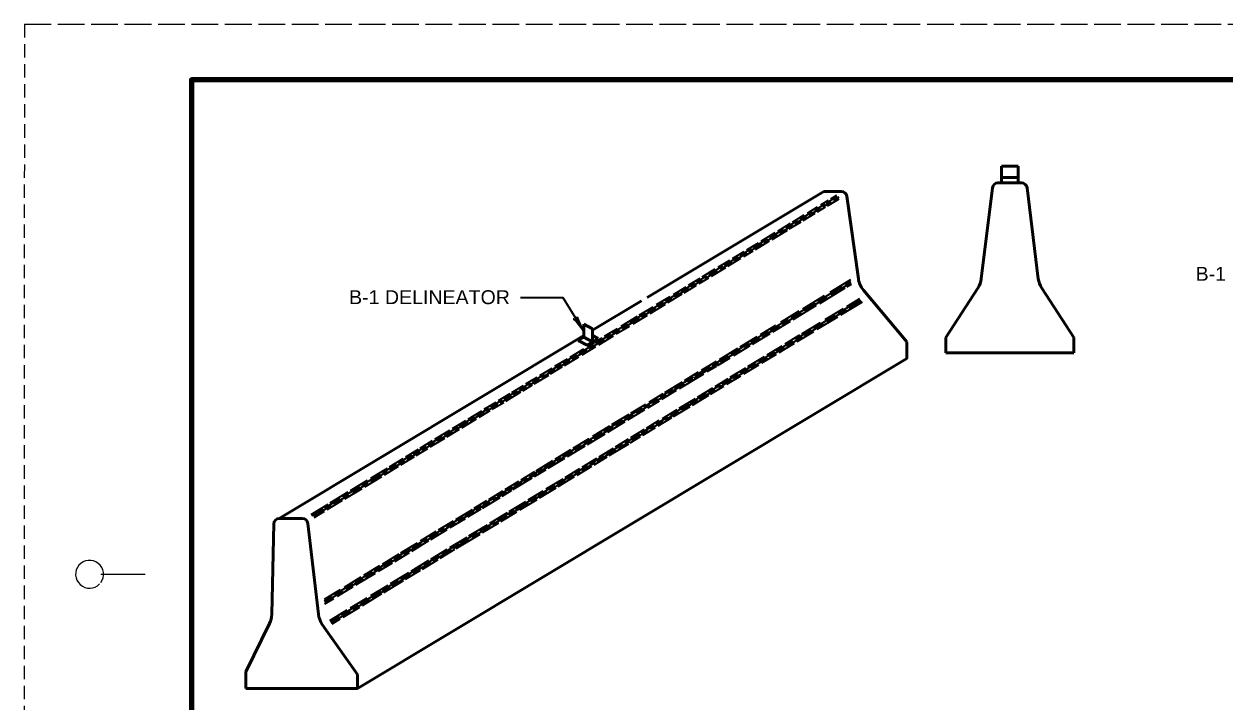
# Model space of a CAD drawing. Extents: x -60 to 620, y -42 to 398.
# Drawn here: x -60.3 to 155.3, y 276.6 to 398.3 of the extents above; entities that cross this region are included whole.
import ezdxf
from ezdxf.enums import TextEntityAlignment as Align

# ---------------------------------------------------------------- set-up
doc = ezdxf.new("R2010")
doc.units = 0
doc.header["$LTSCALE"] = 0.8
doc.linetypes.add('LONG_DASHED', pattern=[7.5, 6, -1.5])
doc.linetypes.add('MEDIUM_DASHED', pattern=[4.5, 3, -1.5])
doc.layers.add('1', color=7, linetype='Continuous', lineweight=35)
doc.layers.add('61', color=7, linetype='Continuous', lineweight=35)

msp = doc.modelspace()

# ---------------------------------------------------------------- linework, layer by layer
at = {"layer": '1', "linetype": 'MEDIUM_DASHED', "lineweight": 13}
msp.add_line((-60.2155, 398.2688), (-60.2755, -41.7713), dxfattribs=at)
at = {"layer": '1', "lineweight": 53}
for p, q in [((115.1369, 372.7462), (115.1369, 369.7462)), ((115.1369, 372.7462), (118.1369, 372.7462)), ((115.1369, 370.7462), (118.1369, 370.7462)), ((118.1369, 372.7462), (118.1369, 369.7462)), ((111.5132, 352.5558), (113.5285, 368.8687)), ((114.521, 369.7462), (118.7528, 369.7462)), ((121.7606, 352.5558), (119.7453, 368.8687)), ((51.5427, 349.1747), (83.2579, 368.231)), ((83.258, 368.2311), (86.3888, 368.2311)), ((87.379, 367.3702), (89.4643, 352.5318)), ((90.3607, 350.5181), (98.1369, 341.2462)), ((105.1369, 341.9962), (110.8982, 350.8678)), ((128.1369, 341.9962), (122.3757, 350.8678)), ((41.7647, 343.2994), (50.5427, 348.5738)), ((40.2022, 342.0675), (40.2022, 344.4112)), ((40.2022, 344.4112), (41.7647, 343.5703)), ((41.7647, 341.2266), (41.7647, 343.5703)), ((-14.4591, 309.5168), (40.2022, 342.3607)), ((39.1975, 341.4638), (40.2022, 342.0675)), ((39.1975, 341.4638), (40.7686, 340.6088)), ((40.2022, 342.0675), (41.7647, 341.2266)), ((40.7629, 340.6182), (41.7647, 341.2266)), ((41.7592, 341.2359), (42.7609, 341.8442)), ((41.7647, 342.3864), (42.7609, 341.8442)), ((105.1369, 339.2462), (105.1369, 341.9962)), ((128.1369, 339.2462), (128.1369, 341.9962)), ((105.1369, 339.2462), (128.1369, 339.2462)), ((-15.8152, 292.3312), (-15.4588, 308.5387)), ((-14.4591, 309.5168), (-10.3276, 309.5168)), ((-7.4372, 292.3503), (-9.3343, 308.6325)), ((-20.4373, 282.0168), (-16.219, 290.6656)), ((-0.4373, 281.5168), (-6.7407, 290.5188)), ((-20.4373, 279.0168), (-20.4373, 282.0168)), ((-0.4373, 279.0168), (-0.4373, 281.5168)), ((-20.4373, 279.0168), (-0.4373, 279.0168))]:
    msp.add_line(p, q, dxfattribs=at)
at = {"layer": '1'}
for p, q in [((82.7095, 365.7921), (84.1125, 366.644)), ((83.7058, 366.1046), (85.6554, 367.2884)), ((83.9053, 365.6407), (85.9958, 366.9101)), ((84.5417, 366.9047), (85.572, 367.5302)), ((85.0686, 366.6396), (86.0474, 367.2339)), ((79.0243, 363.2619), (81.1655, 364.5621)), ((79.5882, 363.0192), (81.7362, 364.3236)), ((80.317, 364.3393), (82.1538, 365.4547)), ((80.6573, 363.961), (82.727, 365.2177)), ((81.6363, 364.8479), (83.482, 365.9687)), ((82.1379, 364.5675), (83.5915, 365.4502)), ((83.1213, 365.4572), (84.6097, 366.361)), ((75.0146, 361.1196), (77.3105, 362.5138)), ((75.3733, 360.7525), (77.6758, 362.1506)), ((76.5091, 361.7346), (78.6042, 363.0068)), ((77.0618, 361.4853), (79.1799, 362.7714)), ((77.6497, 362.7197), (79.7679, 364.0059)), ((78.149, 362.4379), (80.2372, 363.7058)), ((72.0462, 359.3171), (74.5393, 360.831)), ((72.564, 359.0467), (74.9811, 360.5143)), ((73.5511, 359.9384), (76.0314, 361.4445)), ((73.9928, 359.6217), (76.72, 361.2777)), ((68.2706, 356.7321), (70.2956, 357.9617)), ((69.4199, 357.7223), (71.5307, 359.0041)), ((69.871, 357.4115), (72.189, 358.819)), ((70.6348, 358.1677), (73.1818, 359.7142)), ((71.0264, 357.8205), (73.5382, 359.3457)), ((64.3326, 354.6332), (66.3972, 355.8869)), ((65.4373, 355.0117), (67.8893, 356.5006)), ((66.0403, 354.7928), (68.3869, 356.2177)), ((66.9039, 356.1946), (68.9752, 357.4522)), ((67.2186, 355.8009), (69.5362, 357.2082)), ((68.8917, 356.5242), (70.566, 357.5409)), ((61.453, 352.8847), (63.7905, 354.3041)), ((61.9748, 352.6167), (64.1997, 353.9677)), ((62.6412, 353.3137), (65.1529, 354.8389)), ((63.1273, 353.024), (65.6833, 354.5761)), ((64.7087, 354.2769), (66.813, 355.5546)), ((57.667, 350.2933), (60.1002, 351.7708)), ((58.1795, 350.0196), (60.4123, 351.3754)), ((58.9768, 351.3812), (61.05, 352.64)), ((59.4439, 351.08), (61.5217, 352.3417)), ((60.451, 351.9838), (62.2686, 353.0875)), ((60.9062, 351.6753), (62.6182, 352.7149)), ((84.3843, 350.1377), (88.0927, 352.3895)), ((84.5558, 349.6568), (88.1685, 351.8505)), ((87.1312, 351.513), (88.1307, 352.1199)), ((87.4198, 351.1035), (88.2098, 351.5832)), ((53.2662, 347.9136), (55.6943, 349.388)), ((54.8354, 348.574), (57.3162, 350.0804)), ((55.2881, 348.2638), (57.867, 349.8297)), ((56.2621, 349.7328), (58.5403, 351.1162)), ((56.5431, 349.3186), (59.0574, 350.8453)), ((79.4742, 347.1562), (83.3711, 349.5224)), ((79.8356, 346.7906), (83.8847, 349.2492)), ((82.221, 348.5315), (86.5327, 351.1496)), ((82.522, 348.1295), (87.0777, 350.8957)), ((50.15, 346.0214), (52.6122, 347.5165)), ((50.5763, 345.6954), (53.1458, 347.2557)), ((51.6934, 346.6662), (54.4914, 348.3652)), ((52.0862, 346.3196), (54.8656, 348.0072)), ((53.5778, 347.518), (56.0683, 349.0302)), ((77.4281, 345.6212), (81.7329, 348.2352)), ((77.7449, 345.2287), (81.9681, 347.7931)), ((83.4892, 345.2069), (86.7786, 347.2043)), ((85.8528, 346.3497), (89.8738, 348.7912)), ((86.3438, 346.0628), (90.1988, 348.4037)), ((87.3866, 347.5735), (89.7112, 348.9851)), ((87.8146, 347.2483), (90.0363, 348.5974)), ((46.9054, 344.0512), (49.7972, 345.8072)), ((47.1507, 343.6153), (50.1759, 345.4522)), ((48.4893, 344.7207), (51.2899, 346.4212)), ((49.0588, 344.4813), (51.5948, 346.0213)), ((73.6775, 343.3438), (76.8702, 345.2823)), ((74.0979, 343.0143), (77.2602, 344.9344)), ((75.5359, 344.7648), (78.8249, 346.7619)), ((75.8467, 344.3684), (79.2529, 346.4367)), ((81.4554, 343.6795), (85.305, 346.017)), ((82.0862, 343.4776), (85.7741, 345.7169)), ((83.8669, 344.8512), (87.3238, 346.9502)), ((43.9002, 342.2264), (46.2312, 343.6418)), ((44.3267, 341.9006), (46.6382, 343.3042)), ((45.3607, 342.8209), (48.0362, 344.4455)), ((46.0281, 342.641), (48.365, 344.06)), ((70.19, 341.2261), (73.3333, 343.1347)), ((70.4884, 340.8225), (73.6143, 342.7206)), ((71.8853, 342.5481), (74.6733, 344.241)), ((72.2699, 342.1966), (75.3515, 344.0677)), ((78.1838, 341.6928), (81.0057, 343.4064)), ((78.5059, 341.3036), (81.4528, 343.093)), ((79.3247, 342.6782), (82.6405, 344.6916)), ((79.7837, 342.3719), (83.2048, 344.4493)), ((39.3402, 339.1651), (41.9953, 340.7773)), ((40.8491, 340.3737), (43.4779, 341.97)), ((41.2204, 340.0144), (43.8973, 341.6398)), ((42.3722, 341.0062), (45.0273, 342.6184)), ((42.8603, 340.7174), (45.5155, 342.3297)), ((66.6608, 339.0831), (69.8221, 341.0027)), ((67.1107, 338.7715), (70.0523, 340.5577)), ((68.2643, 340.3493), (71.3041, 342.1952)), ((69.0316, 340.2303), (71.7599, 341.8869)), ((74.7675, 339.6184), (77.677, 341.3851)), ((75.2291, 339.3138), (78.0023, 340.9977)), ((76.326, 340.8574), (78.9598, 342.4567)), ((76.6161, 340.4485), (79.4189, 342.1504)), ((36.4969, 337.4387), (38.968, 338.9392)), ((36.7063, 336.9807), (39.3137, 338.5639)), ((37.745, 338.4889), (40.2245, 339.9945)), ((38.1238, 338.1341), (40.7962, 339.7568)), ((39.8763, 338.9055), (42.3406, 340.4018)), ((63.2017, 336.9827), (66.1239, 338.7571)), ((64.5349, 338.0848), (67.834, 340.0881)), ((64.7141, 337.6087), (68.2929, 339.7818)), ((69.636, 336.7952), (72.622, 338.6083)), ((71.6299, 337.7133), (74.4291, 339.4129)), ((72.1565, 337.4482), (74.7634, 339.0312)), ((73.1114, 338.9055), (75.7955, 340.5352)), ((73.5435, 338.5828), (76.198, 340.1947)), ((32.2762, 335.1683), (34.509, 336.5241)), ((32.6422, 334.8056), (35.0575, 336.2722)), ((33.7278, 335.7572), (36.1197, 337.2097)), ((34.2228, 335.4727), (36.3932, 336.7905)), ((35.0178, 336.833), (37.2362, 338.18)), ((35.4147, 336.4891), (37.7367, 337.899)), ((60.0748, 334.7917), (64.3996, 337.4178)), ((60.1217, 335.1125), (62.8872, 336.7917)), ((61.3113, 336.1274), (64.0087, 337.7653)), ((62.3523, 335.8822), (64.0044, 336.8853)), ((64.197, 337.0023), (66.4608, 338.3769)), ((66.4467, 334.8586), (69.2756, 336.5763)), ((67.0792, 334.6576), (69.7692, 336.291)), ((68.2933, 335.6872), (71.0424, 337.3565)), ((68.9204, 335.4832), (71.599, 337.1096)), ((70.2004, 336.5528), (73.146, 338.3414)), ((29.7993, 333.6642), (31.8408, 334.9039)), ((30.3017, 333.3843), (32.213, 334.5449)), ((31.0119, 334.1081), (33.1593, 335.412)), ((31.2573, 333.672), (33.8914, 335.2715)), ((56.4812, 332.902), (59.89, 334.9718)), ((57.3891, 332.8684), (61.7312, 335.505)), ((58.2777, 334.2854), (60.7948, 335.8137)), ((58.8663, 334.0578), (59.8162, 334.6347)), ((63.7788, 333.2386), (66.1227, 334.6618)), ((64.4156, 333.0403), (66.6723, 334.4106)), ((65.0037, 333.6898), (67.8521, 335.4193)), ((65.8721, 333.6322), (68.3505, 335.1371)), ((24.9042, 330.6919), (26.9522, 331.9355)), ((25.8838, 330.9942), (28.2502, 332.4311)), ((26.1965, 330.599), (28.8851, 332.2315)), ((27.3006, 332.147), (29.3876, 333.4142)), ((27.5853, 331.7349), (29.8843, 333.1309)), ((28.652, 332.6751), (30.6281, 333.875)), ((29.2453, 332.4502), (30.9664, 333.4953)), ((51.9203, 330.4251), (54.4504, 331.9614)), ((53.9208, 331.3473), (56.1863, 332.7229)), ((54.2152, 330.9412), (56.8212, 332.5237)), ((54.742, 332.1384), (57.9, 334.056)), ((55.3786, 331.94), (58.2669, 333.6938)), ((59.307, 330.2306), (62.2014, 331.9881)), ((60.616, 331.3181), (63.3742, 332.9928)), ((60.9365, 330.9277), (63.7533, 332.6381)), ((62.567, 332.2101), (64.7479, 333.5343)), ((62.9487, 331.8571), (65.2973, 333.2833)), ((22.3254, 329.126), (24.4711, 330.4289)), ((22.7447, 328.7957), (24.8271, 330.0601)), ((23.4759, 329.5321), (25.5535, 330.7937)), ((23.7607, 329.12), (25.8126, 330.3659)), ((25.201, 330.2872), (27.2666, 331.5414)), ((48.6373, 328.4316), (51.3347, 330.0694)), ((49.66, 328.4676), (52.0928, 329.9448)), ((50.9945, 329.5704), (53.4824, 331.0811)), ((51.6678, 329.3944), (53.7568, 330.6629)), ((52.5064, 330.196), (55.0018, 331.7113)), ((55.7422, 328.0659), (59.1118, 330.1121)), ((57.3169, 329.3148), (60.2187, 331.0768)), ((57.8128, 329.0309), (60.6612, 330.7605)), ((59.6835, 329.8744), (62.6268, 331.6617)), ((17.8907, 326.1407), (20.5613, 327.7623)), ((19.4088, 327.355), (21.8923, 328.863)), ((19.8213, 327.0206), (22.3807, 328.5747)), ((20.9839, 328.0189), (23.1692, 329.3458)), ((21.4056, 327.6899), (23.3769, 328.887)), ((45.2451, 326.3717), (48.3058, 328.2303)), ((45.9309, 326.2032), (49.1115, 328.1346)), ((47.4922, 327.4437), (50.6879, 329.3842)), ((48.0932, 327.2238), (51.1593, 329.0856)), ((53.155, 326.495), (55.2911, 327.7921)), ((53.5395, 326.1437), (55.9719, 327.6207)), ((54.3102, 327.4891), (56.9292, 329.0793)), ((54.867, 327.2422), (57.2377, 328.6817)), ((56.2891, 327.8132), (59.2619, 329.6184)), ((15.1841, 324.4972), (17.617, 325.9745)), ((15.5884, 324.1577), (17.9079, 325.5661)), ((16.6094, 325.6552), (19.0258, 327.1225)), ((17.0728, 325.3517), (19.4429, 326.7908)), ((18.3118, 325.8113), (20.9615, 327.4203)), ((41.8039, 324.2822), (44.851, 326.1325)), ((42.0436, 323.8428), (45.4969, 325.9398)), ((43.7707, 325.184), (47.1257, 327.2212)), ((44.4841, 325.0322), (47.6344, 326.9452)), ((48.6283, 324.0388), (51.0849, 325.5306)), ((50.5531, 324.9151), (52.749, 326.2485)), ((50.8123, 324.4878), (53.0509, 325.8471)), ((51.4265, 325.738), (53.7422, 327.1442)), ((52.1772, 325.6088), (54.4503, 326.9892)), ((10.8331, 322.1477), (13.0508, 323.4943)), ((12.2523, 322.7169), (14.7464, 324.2314)), ((12.6286, 322.3604), (15.235, 323.9431)), ((13.4675, 323.7473), (16.1258, 325.3615)), ((13.9245, 323.44), (16.6247, 325.0796)), ((38.29, 322.1486), (41.1663, 323.8951)), ((38.6405, 321.7764), (41.6958, 323.6317)), ((40.1957, 323.0132), (43.5063, 325.0235)), ((40.8258, 322.8109), (43.9977, 324.737)), ((45.8757, 322.3675), (48.2274, 323.7955)), ((46.4507, 322.1316), (48.4797, 323.3637)), ((47.5926, 323.1174), (50.2389, 324.7242)), ((48.5202, 323.0959), (50.3562, 324.2107)), ((48.7997, 323.5579), (51.7037, 325.3213)), ((8.2545, 320.5819), (10.518, 321.9563)), ((8.5042, 320.1487), (10.8167, 321.5528)), ((9.6215, 321.1195), (11.8789, 322.4903)), ((10.1218, 320.8383), (12.2061, 322.1038)), ((11.2047, 321.7885), (13.4495, 323.1515)), ((35.0763, 320.1972), (37.8614, 321.8883)), ((35.4317, 319.828), (38.2497, 321.5391)), ((36.3515, 320.6789), (39.6864, 322.7039)), ((37.2616, 320.6467), (40.4403, 322.5768)), ((42.5857, 319.7847), (45.9462, 321.8252)), ((42.9639, 320.5994), (45.5001, 322.1394)), ((44.1792, 321.0447), (47.2117, 322.8862)), ((44.7616, 320.8137), (48.2428, 322.9275)), ((4.1507, 317.7976), (6.5964, 319.2827)), ((5.3382, 318.8112), (7.757, 320.2798)), ((5.4235, 318.278), (8.0932, 319.8991)), ((6.9564, 319.5012), (9.3386, 320.9477)), ((7.3249, 319.1399), (9.7994, 320.6425)), ((31.6217, 318.0995), (34.6095, 319.9137)), ((32.0692, 317.7862), (35.096, 319.6242)), ((33.0592, 318.6798), (36.0765, 320.5119)), ((33.8082, 318.5497), (36.8102, 320.3726)), ((38.5553, 317.6298), (40.8918, 319.0486)), ((39.8861, 318.7305), (42.5228, 320.3316)), ((39.8987, 318.1532), (42.316, 319.621)), ((41.2876, 319.2889), (43.7883, 320.8074)), ((42.0414, 319.1619), (44.3882, 320.5869)), ((0.3282, 315.4766), (3.648, 317.4923)), ((0.8827, 315.2282), (3.9381, 317.0835)), ((1.9412, 316.1635), (4.9437, 317.9867)), ((1.995, 316.7811), (4.9609, 318.5821)), ((4.4207, 317.3765), (6.9478, 318.911)), ((28.9562, 316.481), (31.3761, 317.9504)), ((29.4479, 316.1946), (31.7932, 317.6187)), ((30.4367, 317.0873), (32.7716, 318.5052)), ((31.3424, 317.0524), (33.4147, 318.3107)), ((35.4672, 315.7547), (38.2426, 317.4399)), ((35.5959, 315.2481), (38.5324, 317.0312)), ((36.8411, 316.8815), (39.4751, 318.4809)), ((37.2948, 316.572), (39.5609, 317.948)), ((38.9735, 317.299), (41.6609, 318.9308)), ((-3.0745, 313.4104), (-0.0261, 315.2614)), ((-2.7078, 313.048), (0.3935, 314.9312)), ((-1.6814, 314.5487), (1.3504, 316.3897)), ((-1.2796, 314.2077), (1.4686, 315.8765)), ((24.6424, 313.569), (27.3713, 315.226)), ((26.0701, 314.7285), (28.5092, 316.2096)), ((26.6252, 314.4806), (29.1331, 316.0034)), ((27.4795, 314.7067), (30.9313, 316.8028)), ((27.7244, 315.4404), (30.0201, 316.8344)), ((32.0238, 313.6638), (35.0086, 315.4762)), ((32.2227, 313.1998), (35.2428, 315.0337)), ((33.4593, 314.8281), (36.4578, 316.6488)), ((34.0617, 314.6088), (36.9117, 316.3393)), ((-6.2853, 311.4607), (-3.5342, 313.1313)), ((-5.8592, 311.1344), (-3.0917, 312.8149)), ((-5.309, 312.346), (-2.0953, 314.2974)), ((-4.6422, 312.1658), (-1.9706, 313.7882)), ((20.5269, 311.3626), (22.7783, 312.7297)), ((22.0384, 311.4028), (25.1617, 313.2993)), ((22.1424, 312.051), (24.416, 313.4316)), ((23.1482, 312.9543), (25.6507, 314.4738)), ((23.9101, 312.8319), (26.3851, 314.3347)), ((25.5261, 313.5206), (27.2835, 314.5877)), ((26.7879, 310.7772), (29.7869, 312.5983)), ((27.9374, 311.1825), (31.7394, 313.4912)), ((28.6962, 311.0585), (31.7979, 312.9418)), ((30.1872, 312.8413), (32.9048, 314.4914)), ((30.6677, 312.5479), (33.6202, 314.3407)), ((-8.7566, 310.2526), (-5.6928, 312.113)), ((-8.6058, 310.0517), (-6.6126, 311.262)), ((-8.283, 309.9552), (-5.1284, 311.8707)), ((-8.1818, 309.7241), (-6.3454, 310.8392)), ((17.2322, 309.362), (20.1982, 311.1631)), ((17.6347, 309.0214), (20.5132, 310.7693)), ((18.8483, 310.0507), (21.7809, 311.8314)), ((19.3896, 309.7944), (21.7624, 311.2353)), ((20.8998, 311.004), (23.3418, 312.4869)), ((23.3468, 308.6877), (26.4761, 310.5877)), ((24.6898, 309.2105), (27.6972, 311.0366)), ((25.2777, 308.9828), (28.1501, 310.7268)), ((26.7468, 310.1671), (30.2538, 312.2965)), ((14.0968, 307.4582), (16.8211, 309.1123)), ((14.5174, 307.1286), (17.1708, 308.7398)), ((15.5761, 308.0637), (18.5638, 309.8779)), ((16.2348, 307.8788), (18.9617, 309.5347)), ((19.5777, 306.399), (22.8778, 308.4029)), ((21.5965, 307.3322), (24.3422, 308.9993)), ((21.986, 306.9839), (24.9109, 308.7599)), ((23.8722, 308.4216), (26.435, 309.9778)), ((10.8868, 305.509), (13.7125, 307.2247)), ((11.5322, 305.3159), (14.089, 306.8685)), ((12.4809, 306.1843), (15.1218, 307.7879)), ((12.7512, 305.7636), (15.6964, 307.5519)), ((16.1487, 304.3168), (19.2329, 306.1897)), ((17.2925, 304.1339), (21.5612, 306.7259)), ((18.0317, 305.1676), (21.0916, 307.0256)), ((20.1275, 306.1477), (23.4497, 308.1651)), ((6.1451, 302.3371), (9.0941, 304.1277)), ((7.3632, 303.3695), (10.3256, 305.1683)), ((7.9158, 303.12), (11.0904, 305.0477)), ((9.3204, 303.6803), (12.4023, 305.5517)), ((9.4078, 304.3182), (12.0927, 305.9486)), ((12.7312, 302.2417), (15.6677, 304.0247)), ((14.4148, 302.3866), (17.0661, 303.9964)), ((14.7363, 303.1666), (17.7915, 305.0218)), ((16.8208, 304.1398), (19.5837, 305.8176)), ((2.6387, 300.208), (5.7827, 302.1171)), ((4.0424, 301.353), (7.0362, 303.1709)), ((4.3129, 300.9323), (7.5095, 302.8732)), ((6.2606, 301.8223), (8.9361, 303.447)), ((9.1951, 300.0945), (12.3956, 302.0378)), ((11.2229, 300.4484), (14.0266, 302.1508)), ((11.5397, 301.2256), (14.2906, 302.896)), ((13.1479, 301.9097), (16.3751, 303.8692)), ((-0.8935, 298.0632), (2.241, 299.9665)), ((-0.7025, 297.5942), (2.7944, 299.7176)), ((0.7263, 299.3394), (3.5567, 301.0581)), ((1.0588, 298.9563), (3.9505, 300.7122)), ((3.3242, 300.0392), (5.859, 301.5784)), ((5.4678, 297.8313), (8.7752, 299.8396)), ((7.3762, 298.6975), (11.0539, 300.9307)), ((8.2118, 298.62), (10.8653, 300.2312)), ((9.5889, 299.7486), (12.7635, 301.6762)), ((-4.5318, 295.8539), (-1.2645, 297.8379)), ((-2.7877, 297.2056), (0.2319, 299.0392)), ((-2.4599, 296.8197), (0.6124, 298.6852)), ((1.993, 295.7212), (5.0615, 297.5845)), ((4.0382, 296.6706), (6.9126, 298.4159)), ((4.2991, 296.2442), (7.8055, 298.3732)), ((5.7737, 297.4319), (9.1338, 299.4722)), ((-6.3762, 295.0266), (-3.4818, 296.7841)), ((-6.3444, 294.7533), (-5.0137, 295.5613)), ((-6.3126, 294.4803), (-3.0479, 296.4626)), ((-4.0406, 295.5673), (-1.2016, 297.2912)), ((-1.6635, 293.501), (1.2911, 295.2951)), ((0.0902, 294.2732), (3.7686, 296.5068)), ((0.4753, 293.9222), (3.9463, 296.0298)), ((2.2013, 295.2627), (5.4247, 297.22)), ((-6.2807, 294.2071), (-4.6812, 295.1783)), ((-5.4091, 291.2267), (-2.2506, 293.1445)), ((-3.2919, 292.2196), (-0.2761, 294.0508)), ((-3.0216, 291.7989), (-0.0191, 293.6221)), ((-1.1894, 293.2038), (1.7643, 294.9974)), ((-5.2653, 291.0213), (-3.7337, 291.9514)), ((-5.1217, 290.8162), (-1.6799, 292.9061)), ((-4.978, 290.6109), (-3.5427, 291.4825))]:
    msp.add_line(p, q, dxfattribs=at)
msp.add_lwpolyline([(28.8323, 349.1562), (36.3999, 349.1562), (40.2022, 343.0958)], dxfattribs=at)
at = {"layer": '1', "lineweight": 53}
msp.add_lwpolyline([(-0.4373, 279.0168), (98.1369, 338.2462), (98.1369, 341.2462)], dxfattribs=at)
for centre, radius, start, end in [((114.521, 368.7462), 1, 90, 172.95699), ((118.7529, 368.7462), 1, 7.04303, 90), ((86.3887, 367.2311), 1, 8.00018, 90), ((93.4254, 353.0885), 4, 188.00017, 219.98679), ((107.5435, 353.0463), 4, 327.00063, 352.95779), ((125.7304, 353.0463), 4, 187.04242, 212.99913), ((-14.4591, 308.5168), 1, 90, 178.73944), ((-10.3276, 308.5168), 1, 6.64453, 90), ((-19.8142, 292.4191), 4, 333.99969, 358.74001), ((-3.4641, 292.8131), 4, 186.64528, 214.99909)]:
    msp.add_arc(centre, radius, start, end, dxfattribs=at)
at = {"layer": '1', "lineweight": 40}
for centre, major_axis, ratio, start_param, end_param in [((39.3882, 343.8733), (1.0813, -1.4297), 0.122415, 0.89635335, 3.14159265), ((39.7859, 344.1574), (0.7847, -1.5812), 0.07063, 3.14071475, 5.41810995)]:
    msp.add_ellipse(centre, major_axis=major_axis, ratio=ratio, start_param=start_param, end_param=end_param, dxfattribs=at)
at = {"layer": '61', "linetype": 'LONG_DASHED', "lineweight": 13}
msp.add_line((-60.2155, 398.2688), (619.8045, 398.2688), dxfattribs=at)
at = {"layer": '61', "lineweight": 13}
msp.add_line((-46.4955, 299.5087), (-38.5155, 299.5288), dxfattribs=at)
at = {"layer": '61', "lineweight": 158}
msp.add_lwpolyline([(608.8245, 388.2688), (-30.2155, 388.2688), (-30.2155, -31.7512)], dxfattribs=at)
at = {"layer": '61', "lineweight": 13}
msp.add_arc((-48.5177, 299.51), 2.5, 323.13009, 316.23216, dxfattribs=at)

# ---------------------------------------------------------------- texts
at = {"layer": '1', "width": 1.05}
msp.add_text('B-1 DELINEATOR', height=2.5, dxfattribs=at).set_placement((149.9911, 352.1882))
msp.add_text('B-1 DELINEATOR', height=2.5, dxfattribs=at).set_placement((12.4942, 347.9925), align=Align.CENTER)

doc.saveas('drawing.dxf')
